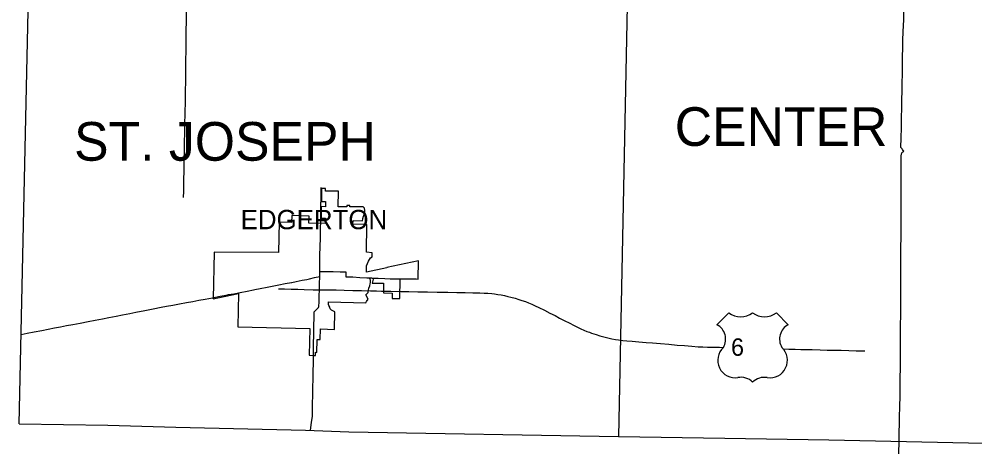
# Model space of a CAD drawing. Extents: x -232 to 448, y 619 to 1059.
# Drawn here: x -182.3 to -131.6, y 850.9 to 874 of the extents above; entities that cross this region are included whole.
import ezdxf

# ---------------------------------------------------------------- set-up
doc = ezdxf.new("R2010")
doc.units = 0
doc.layers.add('Default', color=7, linetype='Continuous')

msp = doc.modelspace()

# ---------------------------------------------------------------- linework, layer by layer
at = {"layer": 'Default'}
for p, q in [((-166.206, 865.007), (-166.218, 864.303)), ((-166.008, 865.007), (-166.206, 865.007)), ((-166.008, 864.853), (-166.008, 865.007)), ((-165.32, 864.853), (-166.008, 864.853)), ((-165.321, 864.033), (-165.32, 864.853)), ((-166.227, 864.037), (-166.236, 863.42)), ((-166.007, 864.034), (-166.227, 864.037)), ((-166.218, 864.303), (-166.008, 864.303)), ((-166.008, 864.303), (-166.007, 864.034)), ((-164.871, 864.029), (-165.321, 864.033)), ((-164.869, 864.089), (-164.871, 864.029)), ((-164.715, 864.089), (-164.869, 864.089)), ((-164.715, 864.017), (-164.715, 864.089)), ((-164.008, 864.017), (-164.715, 864.017)), ((-167.786, 863.56), (-167.796, 863.19)), ((-166.872, 863.536), (-167.786, 863.56)), ((-166.881, 863.167), (-166.872, 863.536)), ((-166.236, 863.42), (-166.008, 863.42)), ((-166.008, 863.42), (-166.008, 863.145)), ((-164.545, 863.107), (-164.539, 863.302)), ((-164.539, 863.302), (-164.046, 863.288)), ((-161.072, 861.158), (-162.752, 860.81)), ((-161.092, 860.195), (-161.072, 861.158)), ((-162.751, 860.782), (-163.818, 860.551)), ((-162.752, 860.81), (-162.751, 860.782)), ((-163.533, 859.976), (-162.916, 859.969)), ((-162.916, 859.969), (-162.926, 859.456)), ((-162.06, 859.153), (-162.038, 860.204)), ((-162.926, 859.456), (-162.465, 859.446)), ((-162.465, 859.446), (-162.47, 859.161)), ((-162.47, 859.161), (-162.06, 859.153)), ((-165.526, 857.52), (-165.5, 858.46)), ((-144.604, 858.404), (-145.238, 857.77)), ((-144.604, 858.404), (-145.238, 857.77)), ((-141.449, 857.77), (-142.083, 858.404)), ((-141.449, 857.77), (-142.083, 858.404)), ((-166.83, 857.569), (-166.869, 856.149)), ((-166.28, 856.982), (-166.268, 857.542)), ((-166.268, 857.542), (-165.526, 857.52)), ((-166.454, 856.302), (-166.436, 856.986)), ((-166.436, 856.986), (-166.28, 856.982)), ((-166.663, 856.143), (-166.535, 856.141)), ((-166.535, 856.141), (-166.531, 856.304)), ((-166.531, 856.304), (-166.454, 856.302))]:
    msp.add_line(p, q, dxfattribs=at)
for points in [[(-182.255, 852.514), (-181.536, 884.982)], [(-149.809, 884.388), (-150.45, 851.844)], [(-173.527, 864.527), (-173.519, 864.856), (-173.513, 865.417), (-173.501, 865.969), (-173.492, 866.485), (-173.485, 867.034), (-173.476, 867.531), (-173.464, 867.888), (-173.46, 868.372), (-173.447, 869.015), (-173.436, 869.621), (-173.427, 870.202), (-173.416, 870.667), (-173.413, 871.261), (-173.405, 871.814), (-173.399, 872.307), (-173.393, 872.843), (-173.387, 873.349), (-173.375, 873.889), (-173.371, 874.37), (-173.368, 874.853), (-173.364, 875.072)], [(-135.578, 850.913), (-135.566, 851.61), (-135.559, 852.105), (-135.548, 852.467), (-135.545, 852.861), (-135.533, 853.436), (-135.523, 853.974), (-135.514, 854.486), (-135.507, 854.973), (-135.503, 855.439), (-135.501, 855.912), (-135.494, 856.343), (-135.496, 856.97), (-135.49, 857.701), (-135.488, 858.307), (-135.482, 858.911), (-135.481, 859.536), (-135.477, 860.206), (-135.474, 860.775), (-135.474, 861.377), (-135.475, 861.84), (-135.469, 862.444), (-135.467, 863.114), (-135.466, 863.687), (-135.463, 864.314), (-135.46, 864.967), (-135.456, 865.555), (-135.455, 866.081), (-135.455, 866.525), (-135.456, 866.765), (-135.449, 866.803), (-135.419, 866.885), (-135.369, 866.941), (-135.317, 866.982), (-135.36, 867.023), (-135.382, 867.061), (-135.408, 867.109), (-135.436, 867.146), (-135.475, 867.181), (-135.459, 867.688), (-135.445, 868.21), (-135.436, 868.766), (-135.432, 869.265), (-135.42, 869.725), (-135.415, 870.161), (-135.407, 870.605), (-135.399, 871.061), (-135.39, 871.51), (-135.382, 871.987), (-135.375, 872.47), (-135.365, 872.86), (-135.347, 873.324), (-135.324, 873.944), (-135.316, 874.402)], [(-166.238, 864.339), (-166.231, 864.774), (-166.225, 865.044)], [(-166.254, 863.474), (-166.252, 863.642), (-166.243, 864.068)], [(-166.243, 864.068), (-166.24, 864.213), (-166.238, 864.339)], [(-164.005, 863.48), (-163.916, 863.702), (-163.91, 863.827), (-163.936, 863.949), (-164.008, 864.017)], [(-168.464, 863.207), (-168.503, 861.602)], [(-167.796, 863.19), (-168.464, 863.207)], [(-166.008, 863.145), (-166.881, 863.167)], [(-166.293, 861.465), (-166.28, 861.902), (-166.273, 862.374), (-166.267, 862.787), (-166.261, 862.984)], [(-166.261, 862.984), (-166.257, 863.137), (-166.256, 863.202)], [(-166.256, 863.202), (-166.254, 863.474)], [(-163.801, 863.088), (-164.545, 863.107)], [(-164.046, 863.288), (-164.022, 863.39)], [(-164.022, 863.39), (-164.016, 863.411), (-164.015, 863.424), (-164.01, 863.449), (-164.005, 863.48)], [(-163.818, 860.551), (-163.831, 860.669), (-163.819, 860.889), (-163.726, 861.15), (-163.621, 861.325), (-163.528, 861.372), (-163.526, 861.588), (-163.818, 861.619), (-163.801, 863.088)], [(-171.911, 861.624), (-171.965, 859.14), (-170.62, 859.425)], [(-168.503, 861.602), (-171.911, 861.624)], [(-166.304, 860.599), (-166.298, 861.022), (-166.293, 861.46), (-166.293, 861.465)], [(-166.31, 860.321), (-166.304, 860.599)], [(-166.304, 860.599), (-165.942, 860.592), (-165.601, 860.586), (-165.22, 860.583), (-164.916, 860.578), (-164.917, 860.556)], [(-164.917, 860.556), (-164.924, 860.319), (-164.886, 860.317)], [(-169.755, 859.632), (-169.471, 859.69), (-169.096, 859.764), (-168.75, 859.827), (-168.476, 859.884), (-168.135, 859.949), (-167.809, 860.012), (-167.788, 860.016)], [(-167.788, 860.016), (-167.554, 860.062), (-167.237, 860.127), (-166.989, 860.177), (-166.842, 860.211), (-166.581, 860.27), (-166.31, 860.321)], [(-166.599, 858.461), (-166.48, 858.575), (-166.404, 858.649), (-166.378, 858.689), (-166.358, 858.732), (-166.346, 858.787), (-166.342, 858.924), (-166.331, 859.306), (-166.324, 859.627), (-166.319, 859.931), (-166.31, 860.321)], [(-164.886, 860.317), (-164.552, 860.302), (-164.18, 860.28), (-163.812, 860.265), (-163.752, 860.261)], [(-163.861, 859.355), (-163.74, 859.475), (-163.716, 859.602), (-163.702, 859.716), (-163.656, 859.826), (-163.624, 859.945), (-163.613, 860.002), (-163.611, 860.05), (-163.611, 860.12), (-163.638, 860.204), (-163.66, 860.255)], [(-163.752, 860.261), (-163.554, 860.249), (-163.532, 860.248)], [(-163.66, 860.255), (-163.554, 860.249), (-163.452, 860.244)], [(-163.452, 860.244), (-163.467, 860.195), (-163.533, 859.976)], [(-163.532, 860.248), (-163.207, 860.232), (-162.845, 860.223), (-162.563, 860.211), (-162.222, 860.205), (-162.124, 860.205)], [(-162.124, 860.205), (-161.928, 860.204), (-161.523, 860.198), (-161.199, 860.196)], [(-162.038, 860.204), (-161.928, 860.204), (-161.523, 860.198), (-161.188, 860.196), (-161.092, 860.195)], [(-171.14, 859.364), (-170.868, 859.414), (-170.536, 859.477), (-170.151, 859.555), (-169.813, 859.621), (-169.755, 859.632)], [(-168.5, 859.68), (-168.489, 859.679), (-168.181, 859.674), (-167.825, 859.662), (-167.474, 859.649), (-167.133, 859.643), (-166.662, 859.629), (-166.23, 859.624), (-165.813, 859.62), (-165.428, 859.612), (-165.009, 859.604), (-164.544, 859.588), (-164.09, 859.582), (-163.613, 859.57), (-163.288, 859.564), (-163.023, 859.552), (-162.54, 859.548), (-162.01, 859.538), (-161.588, 859.529), (-161.101, 859.523), (-160.595, 859.512), (-160.085, 859.503), (-159.514, 859.494), (-159.031, 859.483), (-158.597, 859.479), (-158.19, 859.466), (-157.818, 859.461), (-157.588, 859.45), (-157.384, 859.44), (-157.185, 859.426), (-157.03, 859.405), (-156.854, 859.377), (-156.677, 859.349), (-156.508, 859.315), (-156.32, 859.274), (-156.162, 859.239), (-155.946, 859.179), (-155.748, 859.115), (-155.579, 859.059), (-155.396, 858.996), (-155.229, 858.933), (-155.048, 858.858), (-154.878, 858.779), (-154.685, 858.685), (-154.383, 858.534), (-154.097, 858.387), (-153.824, 858.25), (-153.58, 858.123), (-153.313, 857.983), (-153.076, 857.863), (-152.817, 857.728), (-152.628, 857.634), (-152.46, 857.555), (-152.291, 857.48), (-152.132, 857.417), (-152, 857.366), (-151.886, 857.326), (-151.642, 857.242), (-151.44, 857.179), (-151.244, 857.13), (-151.026, 857.074), (-150.805, 857.024), (-150.621, 856.987), (-150.455, 856.964), (-150.221, 856.934), (-150.014, 856.918), (-149.733, 856.889), (-149.376, 856.86), (-148.986, 856.829), (-148.647, 856.801), (-148.237, 856.764), (-147.784, 856.729), (-147.347, 856.692), (-146.957, 856.661), (-146.571, 856.629), (-146.236, 856.603), (-145.992, 856.589), (-145.741, 856.582), (-145.402, 856.576), (-145.1, 856.569), (-144.895, 856.562)], [(-182.15, 857.256), (-181.831, 857.316), (-181.46, 857.388), (-181.042, 857.469), (-180.706, 857.532), (-180.383, 857.596), (-180.06, 857.657), (-179.737, 857.721), (-179.409, 857.786), (-179.022, 857.858), (-178.589, 857.941), (-178.212, 858.013), (-177.839, 858.087), (-177.493, 858.154), (-177.112, 858.228), (-176.762, 858.293), (-176.38, 858.371), (-176.055, 858.433), (-175.591, 858.524), (-175.145, 858.611), (-174.714, 858.696), (-174.443, 858.746), (-174.095, 858.813), (-173.747, 858.878), (-173.37, 858.948), (-173.034, 859.009), (-172.719, 859.069), (-172.386, 859.128), (-172.001, 859.202), (-171.589, 859.279), (-171.274, 859.339), (-171.14, 859.364)], [(-170.62, 859.425), (-170.652, 857.66)], [(-165.5, 858.46), (-165.68, 858.538), (-165.745, 858.614), (-165.778, 858.701), (-165.832, 858.781), (-165.839, 858.847), (-165.847, 858.93), (-165.838, 858.98)], [(-165.838, 858.98), (-163.856, 858.928), (-163.823, 858.998), (-163.743, 859.13), (-163.861, 859.355)], [(-166.614, 857.59), (-166.613, 857.705), (-166.606, 858.147), (-166.603, 858.457), (-166.599, 858.461)], [(-170.652, 857.66), (-166.83, 857.569)], [(-166.639, 856.173), (-166.638, 856.271), (-166.63, 856.741), (-166.62, 857.241), (-166.614, 857.59)], [(-141.739, 856.485), (-141.425, 856.479), (-141.077, 856.468), (-140.783, 856.459), (-140.551, 856.454), (-140.183, 856.447), (-139.762, 856.437), (-139.39, 856.426), (-139.039, 856.416), (-138.645, 856.41), (-138.242, 856.399), (-137.84, 856.391), (-137.382, 856.383)], [(-166.869, 856.149), (-166.663, 856.143)], [(-166.791, 852.155), (-166.76, 852.448), (-166.739, 852.583), (-166.722, 852.696), (-166.707, 852.79), (-166.697, 852.913), (-166.69, 853.16), (-166.685, 853.544), (-166.672, 854.039), (-166.666, 854.471), (-166.659, 854.861), (-166.656, 855.243), (-166.643, 855.755), (-166.639, 856.173)], [(-182.255, 852.514), (-177.544, 852.43), (-173.932, 852.335), (-167.065, 852.165), (-164.771, 852.08), (-150.45, 851.844)], [(-150.45, 851.844), (-144.81, 851.751), (-139.291, 851.653), (-131.891, 851.507), (-122.867, 851.316), (-117.47, 851.221)]]:
    msp.add_lwpolyline(points, dxfattribs=at)
for centre, radius, start, end in [((-143.973, 859.205), 1.019, 231.813, 308.187), ((-143.973, 859.205), 1.019, 231.813, 308.187), ((-142.713, 859.205), 1.019, 231.813, 308.187), ((-142.713, 859.205), 1.019, 231.813, 308.187), ((-145.634, 857.004), 0.862, 329.1175, 62.6108), ((-145.634, 857.004), 0.862, 329.1175, 62.6108), ((-141.052, 857.004), 0.862, 117.3892, 210.8825), ((-141.052, 857.004), 0.862, 117.3892, 210.8825), ((-144.26, 855.881), 0.93, 133.0046, 278.7282), ((-144.26, 855.881), 0.93, 133.0046, 278.7282), ((-142.426, 855.881), 0.93, 261.2718, 46.9954), ((-142.426, 855.881), 0.93, 261.2718, 46.9954), ((-143.948, 854.147), 0.832, 43.4177, 101.8742), ((-143.948, 854.147), 0.832, 43.4177, 101.8742), ((-142.722, 854.092), 0.883, 79.9613, 134.7468), ((-142.722, 854.092), 0.883, 79.9613, 134.7468)]:
    msp.add_arc(centre, radius, start, end, dxfattribs=at)

# ---------------------------------------------------------------- texts
for s, height, p in [('CENTER', 2.052, (-147.473, 867.258)), ('ST. JOSEPH', 2.052, (-179.339, 866.473)), ('EDGERTON', 1.026, (-170.503, 862.837)), (' 6 ', 0.9234, (-144.83, 856.12))]:
    msp.add_text(s, height=height, dxfattribs=at).set_placement(p)

doc.saveas('drawing.dxf')
